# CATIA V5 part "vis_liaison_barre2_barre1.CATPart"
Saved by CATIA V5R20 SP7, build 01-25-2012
Part number: skl_vis_liaison_barre2_barre1
Bounding box of the stored display mesh (mm): x -2 to 24, y 31.173 to 31.173, z 10.42 to 10.42
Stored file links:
  J:\IFMA\IAO\système avant mef\vis_liaison_barre2_barre1.CATPart
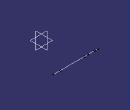
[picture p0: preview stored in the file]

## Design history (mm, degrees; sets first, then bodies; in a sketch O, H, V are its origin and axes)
Body1 (main body)
  Point1 "point_Asecond": stored without definition
  Point2 "Point.A": stored without definition
  Point3 "Point_A_vis": stored without definition
  Point4 "point_Asecond": stored without definition
  Line1: type PtPt, FirstPoint Point3, SecondPoint Point4
  Plane1: stored without definition
  Point5 "Point.A": stored without definition
  Line2 "axe_liaison_barre1_barre2": type Normal, RefPoint Point5, RefSkin Plane1, Start 0, End 20
  Plane2 "Plan_ref": stored without definition
  Point6 "point_Asecond": stored without definition
  Line3 "axe_liaison_barre2_barre1": type Normal, RefPoint Point6, RefSkin Plane2, Start 0, End 20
